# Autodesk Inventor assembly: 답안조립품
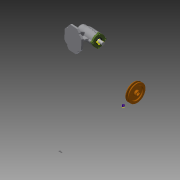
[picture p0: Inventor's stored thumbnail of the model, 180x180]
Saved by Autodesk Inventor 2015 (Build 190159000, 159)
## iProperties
Created: 2019-12
Part Number: 답안조립품
Document SubType Name: Assembly
Designer: now
Author: now
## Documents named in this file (12)
- C:\Users\now\Desktop\491204V1050\답안조립품.iam
- C:\Users\now\Desktop\491204V1050\커버.ipt
- C:\Users\now\Desktop\491204V1050\축.ipt
- C:\Users\now\Desktop\491204V1050\오일 실.ipt
- C:\Users\now\Desktop\491204V1050\어댑터슬리브.ipt
- C:\Users\now\Desktop\491204V1050\볼트 M4.ipt
- C:\Users\now\Desktop\491204V1050\본체.ipt
- C:\Users\now\Desktop\491204V1050\베어링 51202.ipt
- C:\Users\now\Desktop\491204V1050\베어링 6004.ipt
- C:\Users\now\Desktop\491204V1050\멈춤나사 M3.ipt
- C:\Users\now\Desktop\491204V1050\V벨트풀리.ipt
- C:\Users\now\Desktop\491204V1050\Ű 5 x 5 x 16.ipt
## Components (2 placed, 2 different names)
1. V벨트풀리:1
2. Ű 5 x 5 x 16:1 — 각도:1
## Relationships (1: Angle 1)
- 각도:1 [Angle]: Ű 5 x 5 x 16:1
